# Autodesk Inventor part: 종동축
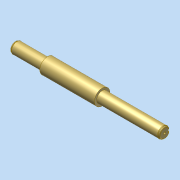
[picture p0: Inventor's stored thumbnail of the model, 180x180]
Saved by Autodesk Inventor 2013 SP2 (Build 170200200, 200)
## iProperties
Created: 2026-01
Part Number: 종동축
Material: Generic
Document SubType Name: Modeling
Designer: a
Density: 1 g/cm^3
Author: a
변환 표준: STEP AP214IS
전처리기: Build: 200, Release: 2013 SP2 Update 6 - Date: Thu 07/17/2014
전송 단위: 밀리미터
불확실성: 0.01
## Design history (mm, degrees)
node "종동축1"
node "솔리드1"
node "기준1"
